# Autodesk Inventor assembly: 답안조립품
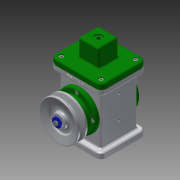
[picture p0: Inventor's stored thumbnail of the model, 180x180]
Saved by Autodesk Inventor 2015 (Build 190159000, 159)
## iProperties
Created: 2017-08
Part Number: 답안조립품
Document SubType Name: Assembly
Designer: Administrator
Author: Administrator
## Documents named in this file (18)
- C:\Users\Administrator\Desktop\470807V1003\답안조립품.iam
- C:\Users\Administrator\Desktop\470807V1003\본체.ipt
- C:\Users\Administrator\Desktop\470807V1003ㅁㅁ\E-링.ipt
- C:\Users\Administrator\Desktop\470807V1003ㅁㅁ\V-벨트풀리.ipt
- C:\Users\Administrator\Desktop\470807V1003ㅁㅁ\덮개.ipt
- C:\Users\Administrator\Desktop\470807V1003ㅁㅁ\뒤커버.ipt
- C:\Users\Administrator\Desktop\470807V1003ㅁㅁ\링크.ipt
- C:\Users\Administrator\Desktop\470807V1003ㅁㅁ\베어링 17 x 40 x 12.ipt
- C:\Users\Administrator\Desktop\470807V1003ㅁㅁ\볼트 M4 x 8.ipt
- C:\Users\Administrator\Desktop\470807V1003ㅁㅁ\볼트 M4 x 10.ipt
- C:\Users\Administrator\Desktop\470807V1003ㅁㅁ\슬라이더.ipt
- C:\Users\Administrator\Desktop\470807V1003ㅁㅁ\앞커버.ipt
- C:\Users\Administrator\Desktop\470807V1003ㅁㅁ\오일 실 17 30 8.ipt
- C:\Users\Administrator\Desktop\470807V1003ㅁㅁ\와셔 4x16.ipt
- C:\Users\Administrator\Desktop\470807V1003ㅁㅁ\클레비스 핀 6 x 22.ipt
- 클레비스 핀 6 x 22.ipt
- C:\Users\Administrator\Desktop\470807V1003ㅁㅁ\키 4 x 4 x 12.ipt
- C:\Users\Administrator\Desktop\470807V1003ㅁㅁ\편심축.ipt
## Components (2 placed, 2 different names)
1. E-링:1
2. V-벨트풀리:1
